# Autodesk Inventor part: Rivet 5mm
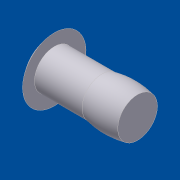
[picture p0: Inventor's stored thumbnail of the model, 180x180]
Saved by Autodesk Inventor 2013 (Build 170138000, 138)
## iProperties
Shininess: 50.0
Length Units: 11269
Angle Units: 11279
Time Units: 11290
Mass Units: 11283
Length Display Precision: 3
Angle Display Precision: 2
Created: 2001-04
Part Number: Rivet 5mm
Material: Standard
Document SubType Name: Modellieren
Designer: dl
Density: 1 g/cm^3
Density: 0.0
Volumn: 0.0
Area: 0.0
PropertySet Name: Model Information
Control State: 0
Master: False
Checked Out: False
Author: dl
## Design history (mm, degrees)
body "Solid1"
sketch "Sketch2"
  geometry: C1 r 1.5 at (0, 0) reference; 1 further point
  constraints: 1 coincident
revolve "Revolution1" stored, may be unused: angle "d8" = 90 deg
hole "Hole1" sketch "Sketch2" diameter "d10" = 2; stored, may be unused: countersink angle "d14" = 60 deg, drill point angle "d16" = 118 deg; dims "d11" = 6, "d12" = 4, "d13" = 2, "d15" = 5
sketch "Sketch1"
  geometry: L1 (0, 4.762)-(0, 6.262); L2 (1.5, 8.762)-(1.5, 7.262); L3 (1.5, 7.262)-(7.5, 7.262); L4 (12, 7.262)-(12, 4.762); L5 (12, 4.762)-(0, 4.762); A1 r 7.508 centre (7.066, 3.722) between (1.5, 8.762) and (0, 6.262); A2 r 10 centre (9.75, -2.482) between (12, 7.262) and (7.5, 7.262)
  constraints: 10 end point, 4 point on circle, 2 centre point, 2 parallel, 1 horizontal, 1 perpendicular, 1 vertical
  dimensions: "d0" = 1.5 distance of L1.start L1.end; "d1" = 4 vertical distance of L1.start L2.start; "d2" = 2.5 distance from line of L4.end L3; "d3" = 1.5 distance between parallel lines of L2 L1; "d4" = 6 distance of L2.end L3.end; "d5" = 10 radius of A2; "d6" = 12 distance of L4.end L1.start; "d7" = 2.25 horizontal distance of L3.end A2.centre
